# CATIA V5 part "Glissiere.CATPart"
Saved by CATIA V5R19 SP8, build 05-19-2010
Part number: glissière
Bounding box of the stored display mesh (mm): x 0 to 30, y -553.4 to 942.5, z 0 to 30
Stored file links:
  G:\EU_thinkMotion\CFAO_2010\MMS_groupe2\MMS_groupe2\A reprendre\rbouchet\rbouchet_Catia\Glissiere.CATPart
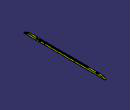
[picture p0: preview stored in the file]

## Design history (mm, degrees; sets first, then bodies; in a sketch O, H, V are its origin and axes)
Body1 (main body)
  Sketch1 on yz-plane, origin (0, 0, 0), H (0, 1, 0), V (0, 0, 1)
    line L1 (-562.5, 0) -> (942.5, 0)
    point P1 (-562.5, 0)
    line L2 (-562.5, 0) -> (-467.1061, 30)
    line L3 (-467.1061, 30) -> (847.1061, 30)
    line L4 (847.1061, 30) -> (942.5, 0)
    length L1 = 1505
    distance P1 V = 562.5
    distance L1 L3 = 30
    length L2 = 100
    length L4 = 100
    coincidence: P1 H
    horizontal: L1 H, L3 H
  Pad1: profile Sketch1, direction (1, 0, 0), length 30
  Fillet1: radius 200, on edge [face of Pad1 from Sketch1.L2 | face of Pad1 from Sketch1.L3]; edge [face of Pad1 from Sketch1.L3 | face of Pad1 from Sketch1.L4]
  Sketch2 on face of Pad1 from Sketch1.L3, origin (0, 0, 30), H (1, 0, 0), V (0, 1, 0)
    line L1 (10.5, -277.5) -> (19.5, -277.5)
    line L2 (19.5, -277.5) -> (19.5, 387.5)
    line L3 (19.5, 387.5) -> (10.5, 387.5)
    line L4 (10.5, 387.5) -> (10.5, -277.5)
    reference projected line E1 (0, -449.4179) -> (0, -524.4179) from edge [start face of Pad1 | face of Fillet1]
    reference projected line E2 (0, -562.5) -> (30, -562.5) from edge [face of Pad1 from Sketch1.L1 | face of Pad1 from Sketch1.L2]
    length L2 = 665
    distance L4 E1 = 10.5
    length L1 = 9
    distance L1 E2 = 285
    horizontal: L1 H, L3 H
    vertical: L2 V, L4 V
  Pocket1: profile Sketch2, direction (0, 0, -1), length 15
  Sketch3 on face of Pocket1 from Sketch2.L1, origin (0, -277.5, 0), H (-1, 0, 0), V (0, 0, 1)
    line L1 (-19.5, 20) -> (-10.5, 20)
    line L2 (-10.5, 20) -> (-10.5, 15)
    line L3 (-10.5, 15) -> (-19.5, 15)
    line L4 (-19.5, 15) -> (-19.5, 20)
    reference projected line E1 (-7.5, 15) -> (-22.5, 15) from edge [end face of Pocket1 | face of Pocket1 from Sketch2.L1]
    reference projected line E2 (-10.5, 30) -> (-10.5, 15) from edge [face of Pocket1 from Sketch2.L4 | face of Pocket1 from Sketch2.L1]
    length L1 = 9
    length L2 = 5
    distance L3 E1 = 0
    distance E2 L2 = 0
    horizontal: L1 H, L3 H
    vertical: L2 V, L4 V
  Pocket2: profile Sketch3, direction (0, -1, 0), length 5
  Fillet2: radius 1, on edge [face of Pocket2 from Sketch3.L2 | end face of Pocket2]; edge [face of Pocket2 from Sketch3.L4 | end face of Pocket2]
  Sketch4 on face of Pad1 from Sketch1.L3, origin (0, 0, 30), H (1, 0, 0), V (0, 1, 0)
    line L1 (7.5, -277.5) -> (22.5, -277.5)
    line L2 (22.5, -277.5) -> (22.5, 617.5)
    line L3 (22.5, 617.5) -> (7.5, 617.5)
    line L4 (7.5, 617.5) -> (7.5, -277.5)
    reference projected line E1 (10.5, -277.5) -> (19.5, -277.5) from edge [face of Pad1 from Sketch1.L3 | face of Pocket1 from Sketch2.L1]
    reference projected line E2 (30, 488.338) -> (30, -488.338) from edge [face of Pad1 from Sketch1.L3 | end face of Pad1]
    distance L1 E1 = 0
    length L1 = 15
    distance L2 E2 = 7.5
    length L2 = 895
    horizontal: L1 H, L3 H
    vertical: L2 V, L4 V
  Pocket3: profile Sketch4, direction (0, 0, -1), length 5
  Sketch5 on face of Pocket2, origin (0, 0, 15), H (1, 0, 0), V (0, 1, 0)
    circle A1 centre (15, 367.5) radius 4.5
    point P1 (15, 367.5)
    reference intersected line E1 (10.5, -348.5) -> (10.5, 316.5) from face of Pocket2
    reference projected line E2 (19.5, 387.5) -> (10.5, 387.5) from edge [end face of Pocket3 | face of Pocket1 from Sketch2.L3]
    radius A1 = 4.5
    distance P1 E1 = 4.5
    distance P1 E2 = 20
  Pocket4: profile Sketch5, direction (0, 0, -1), length 5
  Sketch6 on end face of Pocket4, origin (0, 0, 10), H (1, 0, 0), V (0, 1, 0)
    circle A1 centre (15, 367.5) radius 4
    point P1 (15, 367.5)
    reference projected arc E1 centre (15, 367.5) radius 4.5 from (19.5, 367.5) to (10.5, 367.5) ccw from edge [face of Pocket2 | face of Pocket4 from Sketch5.A1]
    radius A1 = 4
    distance P1 E1 = 4.5
  Pocket5: profile Sketch6, direction (0, 0, -1), length 4
  Fillet3: radius 2, on edge [face of Pocket3 from Sketch4.L4 | face of Pocket3 from Sketch4.L3]; edge [face of Pocket3 from Sketch4.L3 | face of Pocket3 from Sketch4.L2]
  Sketch7 on face of Pad1 from Sketch1.L2, origin (0, -50.625, 160.9772), H (1, 0, 0), V (0, 0.9539, 0.3)
    spline S1 through (0, -433.415) (7.9435, -438.4199) (10.0816, -463.0986) (5.7977, -457.0943) (5.6366, -479.5974) (10.402, -506.7943)
    point P1 (10.402, -506.7943)
    point P2 (12, -536.5908)
    reference projected line E1 (0, -536.5908) -> (30, -536.5908) from edge [face of Pad1 from Sketch1.L1 | face of Pad1 from Sketch1.L2]
    line L1 (10.402, -506.7943) -> (12, -536.5908)
    point P3 (12, -536.5908)
    reference projected line E2 (0, -536.5908) -> (30, -536.5908) from edge [face of Pad1 from Sketch1.L1 | face of Pad1 from Sketch1.L2]
    line L2 (0, -433.415) -> (0, -536.5908)
    point P4 (0, -433.415)
    point P5 (0, -536.5908)
    line L3 (0, -536.5908) -> (12, -536.5908)
    construction line L4 (15, -493.2926) -> (15, -539.8952)
    point P6 (15, -493.2926)
    point P7 (15, -539.8952)
    point P8 (15, -533.2864)
    point P9 (15, -579.889)
    construction line L5 (15, -579.889) -> (15, -533.2864)
    point P10 (18, -536.5908)
    point P11 (30, -536.5908)
    line L6 (30, -536.5908) -> (18, -536.5908)
    point P12 (19.598, -506.7943)
    line L7 (19.598, -506.7943) -> (18, -536.5908)
    spline S2 through (30, -433.415) (22.0565, -438.4199) (19.9184, -463.0986) (24.2023, -457.0943) (24.3634, -479.5974) (19.598, -506.7943)
    line L8 (30, -433.415) -> (30, -536.5908)
    point P13 (30, -433.415)
    axis line L9 (-6.8182, -462.3799) -> (43.7722, -462.3799)
    point P16 (0, -433.415)
    point P17 (10.402, -506.7943)
    point P18 (5.6366, -479.5974)
    point P19 (5.7977, -457.0943)
    point P20 (10.0816, -463.0986)
    point P21 (7.9435, -438.4199)
    point P22 (19.598, -506.7943)
    point P23 (30, -433.415)
    point P24 (24.3634, -479.5974)
    point P25 (24.2023, -457.0943)
    point P26 (19.9184, -463.0986)
    point P27 (22.0565, -438.4199)
    distance E2 P3 = 0
    length L3 = 12
    distance L4 L2 = 15
    coincidence: P16 V, P17 P1, P2 E1, P16 P4, P23 P13
    vertical: L2 V, L4 V, L8 V
    horizontal: L3 H, L9 H
    symmetry: P7 P8 L3, P6 P9 L3, L4 L5 L3, P3 P10 L4, P5 P11 L4, L3 L6 L4, P1 P12 L4, L1 L7 L4, S1 S2 L4, P17 P22 L4, P16 P23 L4, P18 P24 L4, P19 P25 L4, P20 P26 L4, P21 P27 L4
    parallelism: L9 L6
  Pocket6: profile Sketch7, direction (0, 0.3, -0.9539), length 3
  Sketch8 on face of Pad1 from Sketch1.L2, origin (0, -50.625, 160.9772), H (1, 0, 0), V (0, 0.9539, 0.3)
    line L1 (11.4884, -527.0514) -> (18.5116, -527.0514)
    point P1 (11.4884, -527.0514)
    point P2 (18.5116, -527.0514)
    reference projected line E1 (12, -536.5908) -> (11.286, -523.2773) from edge [face of Pad1 from Sketch1.L2 | face of Pocket6 from Sketch7.L1]
    reference projected line E2 (18.714, -523.2773) -> (18, -536.5908) from edge [face of Pad1 from Sketch1.L2 | face of Pocket6 from Sketch7.L7]
    reference projected line E3 (30, -527.0514) -> (18.5381, -527.0514) from edge [end face of Pocket6 | face of Pad1 from Sketch1.L1]
    distance L1 E3 = 0
    horizontal: L1 H
    coincidence: P1 E1, P2 E2
  Pocket7: profile Sketch8, direction (0, 0.3, -0.9539), length 3
  Sketch9 on face of Pad1 from Sketch1.L3, origin (0, 0, 30), H (1, 0, 0), V (0, 1, 0)
    line L1 (12.033, -303.3542) -> (3.9256, -297.5)
    point P1 (12.033, -303.3542)
    point P2 (3.9256, -297.5)
    line L2 (3.9256, -297.5) -> (3.9256, -327.5)
    point P3 (3.9256, -327.5)
    line L3 (3.9256, -327.5) -> (12.033, -333.3542)
    point P4 (12.033, -333.3542)
    line L4 (12.033, -333.3542) -> (12.033, -303.3542)
    point P5 (12.033, -303.3542)
    axis line L5 (15, -332.625) -> (15, -364.7749)
    reference projected line E1 (30, 847.1061) -> (30, -467.1061) from edge [face of Pad1 from Sketch1.L3 | end face of Pad1]
    reference projected line E2 (30, 847.1061) -> (30, -467.1061) from edge [face of Pad1 from Sketch1.L3 | end face of Pad1]
    point P8 (26.0744, -297.5)
    point P9 (17.967, -303.3542)
    line L6 (17.967, -303.3542) -> (26.0744, -297.5)
    point P10 (26.0744, -327.5)
    line L7 (26.0744, -297.5) -> (26.0744, -327.5)
    point P11 (17.967, -303.3542)
    point P12 (17.967, -333.3542)
    line L8 (17.967, -333.3542) -> (17.967, -303.3542)
    line L9 (26.0744, -327.5) -> (17.967, -333.3542)
    reference projected line E3 (10.5, -277.5) -> (19.5, -277.5) from edge [face of Pad1 from Sketch1.L3 | face of Pocket3]
    length L1 = 10
    length L3 = 10
    length L4 = 30
    distance L5 E2 = 15
    distance P2 E3 = 20
    vertical: L2 V, L5 V
    parallelism: L3 L1, L5 E1
    coincidence: P5 L1, P5 P1, P9 P11
    symmetry: P2 P8 L5, P1 P9 L5, L1 L6 L5, P3 P10 L5, L2 L7 L5, P5 P11 L5, P4 P12 L5, L4 L8 L5, L3 L9 L5
  Pocket8: profile Sketch9, direction (0, 0, -1), length 10
  Fillet4: radius 2, on edge [face of Pocket8 from Sketch9.L2 | face of Pocket8 from Sketch9.L1]; edge [face of Pocket8 from Sketch9.L8 | face of Pocket8 from Sketch9.L6]; edge [face of Pocket8 from Sketch9.L1 | face of Pocket8 from Sketch9.L4]; edge [face of Pocket8 from Sketch9.L6 | face of Pocket8 from Sketch9.L7]; edge [face of Pocket8 from Sketch9.L3 | face of Pocket8 from Sketch9.L2]; edge [face of Pocket8 from Sketch9.L9 | face of Pocket8 from Sketch9.L8]; edge [face of Pocket8 from Sketch9.L4 | face of Pocket8 from Sketch9.L3]; edge [face of Pocket8 from Sketch9.L7 | face of Pocket8 from Sketch9.L9]
  Sketch10 on face of Pad1 from Sketch1.L3, origin (0, 0, 30), H (1, 0, 0), V (0, 1, 0)
    circle A1 centre (3.75, -237.5) radius 2
    point P1 (3.75, -237.5)
    reference projected line E1 (0, 847.1061) -> (0, -467.1061) from edge [start face of Pad1 | face of Pad1 from Sketch1.L3]
    reference projected line E2 (10.5, -277.5) -> (19.5, -277.5) from edge [face of Pad1 from Sketch1.L3 | face of Pocket3]
    radius A1 = 2
    distance E1 A1 = 1.75
    distance E2 P1 = 40
  Pocket9: profile Sketch10, direction (0, 0, -1), length 15
  RectPattern1: of Pocket9, direction 1 instances 8, spacing 6, along edge [start face of Pad1 | face of Pad1 from Sketch1.L3], direction 2 instances 2, spacing 22.5, along edge [face of Pad1 from Sketch1.L3 | face of Pocket3]
  Sketch11 on face of Pad1 from Sketch1.L3, origin (0, 0, 30), H (1, 0, 0), V (0, 1, 0)
    circle A1 centre (3.75, -237.4996) radius 2.5
    point P1 (3.75, -237.4996)
    reference projected line E1 (0, 847.1061) -> (0, -467.1061) from edge [start face of Pad1 | face of Pad1 from Sketch1.L3]
    radius A1 = 2.5
    distance P1 E1 = 3.75
  Pocket10: profile Sketch11, direction (0, 0, -1), length 5
  RectPattern2: of Pocket10, direction 1 instances 8, spacing 6, along edge [start face of Pad1 | face of Pad1 from Sketch1.L3], direction 2 instances 2, spacing 22.5, along edge [face of Pad1 from Sketch1.L3 | face of Pocket3]
  Sketch12 on end face of Pocket8, origin (0, 0, 20), H (1, 0, 0), V (0, 1, 0)
    circle A1 centre (7.9953, -315.4574) radius 3.5
    point P1 (7.9953, -315.4574)
    distance P1 A1 = 3.5
  Pocket11: profile Sketch12, direction (0, 0, -1), length 5
  Sketch13 on end face of Pocket11, origin (0, 0, 15), H (1, 0, 0), V (0, 1, 0)
    circle A1 centre (7.9953, -315.4574) radius 3
    reference projected circle E1 centre (7.9953, -315.4574) radius 3.5 from edge [end face of Pocket8 | face of Pocket11 from Sketch12.A1]
    radius A1 = 3
    distance A1 E1 = 0.5
  Pocket12: profile Sketch13, direction (0, 0, -1), through (limit type 6)
  RectPattern3: of Pocket11, Pocket12, direction 1 instances 2, spacing 14, along edge [face of Pad1 from Sketch1.L3 | face of Pocket3], direction 2 instances 2, spacing -1100, along edge [start face of Pad1 | face of Pad1 from Sketch1.L3]
  Sketch14 on face of Pad1 from Sketch1.L3, origin (0, 0, 30), H (1, 0, 0), V (0, 1, 0)
    circle A1 centre (3.7089, -167.5) radius 3.5
    point P1 (3.7089, -167.5)
    reference projected line E1 (10.5, -277.5) -> (19.5, -277.5) from edge [face of Pad1 from Sketch1.L3 | face of Pocket3]
    radius A1 = 3.5
    distance P1 E1 = 110
  Pocket13: profile Sketch14, direction (0, 0, -1), length 5
  Sketch15 on end face of Pocket13, origin (0, 0, 25), H (1, 0, 0), V (0, 1, 0)
    circle A1 centre (3.7089, -167.5) radius 3
    reference projected circle E1 centre (3.7089, -167.5) radius 3.5 from edge [face of Pad1 from Sketch1.L3 | face of Pocket13 from Sketch14.A1]
    radius A1 = 3
    distance A1 E1 = 0.5
  Pocket14: profile Sketch15, direction (0, 0, 1), through (limit type 6)
  RectPattern4: of Pocket13, Pocket14, direction 1 instances 2, spacing 22.5, along edge [face of Pad1 from Sketch1.L3 | face of Pocket3], direction 2 instances 2, spacing -550, along edge [start face of Pad1 | face of Pad1 from Sketch1.L3]
  RectPattern5: of Pocket8, direction 1 instances 2, spacing -1100, along edge [start face of Pad1 | face of Pad1 from Sketch1.L3], direction 2 instances 2, spacing -1100
  Fillet5: radius 2, on edge [face of RectPattern5 | face of RectPattern5] (x8)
